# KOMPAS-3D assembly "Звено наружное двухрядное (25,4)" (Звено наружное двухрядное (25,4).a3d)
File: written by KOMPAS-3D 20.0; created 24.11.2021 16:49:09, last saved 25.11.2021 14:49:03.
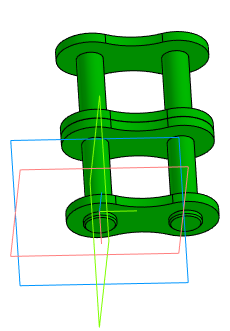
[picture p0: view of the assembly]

Document properties: Полное имя файла: C:\!WORK!\ЗИГ-18.240.00 Линия ЗигЗаг\Цепь\Звено наружное двухрядное  (25,4).a3d

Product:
- Part/product: Звено наружное двухрядное (25,4)
    Масса: 0.110117
  - Component [detail]: Заклепка цепи 8 (61.89)  | pos. 7  | Материал: Сталь 45  ГОСТ 1050-2013 (density 7810 kg/m3); Масса: 0.0249879; source file: Заклепка цепи 8 (61.89).m3d
  - Component [detail]: Заклепка цепи 8 (61.89)  | pos. 5  | Материал: Сталь 45  ГОСТ 1050-2013 (density 7810 kg/m3); Масса: 0.0249879; source file: Заклепка цепи 8 (61.89).m3d
  - Component [detail]: Пластина наружная (25,4)  | pos. 2  | Материал: Сталь 45  ГОСТ 1050-2013 (density 7810 kg/m3); Масса: 0.0150352; source file: Пластина наружная (25,4).m3d
  - Component [detail]: Пластина наружная (25,4)  | pos. 3  | Материал: Сталь 45  ГОСТ 1050-2013 (density 7810 kg/m3); Масса: 0.0150352; source file: Пластина наружная (25,4).m3d
  - Component [detail]: Пластина наружная (25,4)  | pos. 1  | Материал: Сталь 45  ГОСТ 1050-2013 (density 7810 kg/m3); Масса: 0.0150352; source file: Пластина наружная (25,4).m3d
  - Component [detail]: Пластина наружная (25,4)  | pos. 4  | Материал: Сталь 45  ГОСТ 1050-2013 (density 7810 kg/m3); Масса: 0.0150352; source file: Пластина наружная (25,4).m3d

Referenced files in C:\!WORK!\ЗИГ-18.240.00 Линия ЗигЗаг\Цепь\: Пластина наружная (25,4).m3d, Заклепка цепи 8 (61.89).m3d
Referenced files in C:\!WORK!\ЗИГ-18.240.00\Цепь\: Пластина наружная (25,4).m3d, Заклепка цепи 8 (61.89).m3d
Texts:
  Пластина наружная (25,4) (1)
  Пластина наружная (25,4) (2)
  Пластина наружная (25,4) (3)
  Пластина наружная (25,4) (4)
  Заклепка цепи 8 (61.89) (1)
  Заклепка цепи 8 (61.89) (2)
